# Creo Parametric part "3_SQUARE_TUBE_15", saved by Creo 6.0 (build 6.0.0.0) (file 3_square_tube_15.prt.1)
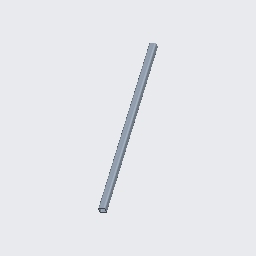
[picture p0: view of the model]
Units: Custom; MM, KILOGRAM, SECS
Materials in the file: STEEL

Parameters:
  BUW_NAME = "SQUARE TUBE"
  BUW_TYPE = "DIN EN 10219"
  BUW_SIZE = "25x25x3.0"
  BUW_LENGTH_STR = "680"
  PTC_MATERIAL_NAME = "STEEL"
  BUW_PROFIL_TYPE = "square_tube"
  BUW_PROFILE_PATH = "parts//profiles/steel_beams_mm/"
  BUW_PROFILE_NAME_LANG = "SQUARE TUBE"
  BUW_TAB_SEL_INFO = "-2 TYPE DIN_EN_10219-1997 SIZE_DINEN_10219 25x25x3.0"
  NAMING = "SQUARE TUBE"
  DESIGNATION = "DIN EN 10219 25x25x3.0 x 680"
  PROFIL_RASTER_POS = "X_0"
  BUW_OBJECT_ROLE = "PROFIL_SYSTEM_BORE_END_POINTS"
  PRO_UNIT_SYS = "Custom"

Other parameters: BUW_LENGTH, LENGTH, BUW_LENGTH_Z_MIN_PARAM, D8, D93, D94, d26, d8, d93, d94, d98, D98, SHEAR_MODULUS, THERM_EXPANSION_REF_TEMPERATURE, STRUCTURAL_DAMPING_COEFFICIENT, STRESS_LIMIT_FOR_TENSION, STRESS_LIMIT_FOR_COMPRESSION, STRESS_LIMIT_FOR_SHEAR, EMISSIVITY

Created from: SQUARE_TUBE.PRT

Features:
  1. datum plane "YZ"
  2. datum plane "XZ"
  3. datum plane "XY"
  4. coordinate system
  5. coordinate system
  6. coordinate system
  7. coordinate system
  8. datum plane "DTM3"
  9. datum plane "DTM4"
  10. datum plane "DTM5"
  11. protrusion
  12. round
  13. round
  14. datum axis
  15. datum point "PNT0"
  16. datum point

Other named items: PROFIL_CUT_QUILT, PROFILE_LENGTH_DIM, CONTACT_SURF_3, CONTACT_SURF_2, CONTACT_SURF_1, CONTACT_SURF_0, E, START_SURFACE, END_SURFACE, SIDE_SURF_3, SIDE_SURF_0, SIDE_SURF_1, SIDE_SURF_2, EDGE_7_S, EDGE_7_E, EDGE_1_S, EDGE_1_E, EDGE_3_S, EDGE_3_E, EDGE_5_S, EDGE_5_E, EDGE_6_S, EDGE_4_S, EDGE_2_S, EDGE_0_S, EDGE_6_E, EDGE_4_E, EDGE_2_E, EDGE_0_E, CS0, CS_S, CS_E, CS3

Named dimensions: X_ROT_S, Y_ROT_S, Z_OFF_S, X_ROT_E, Y_ROT_E, Z_OFF_E, PC_L, BUW_LENGTH_Z_MIN, BUW_LENGTH_DIM

Layers: 00_PROFIL_DATUM, 00_PROFIL_DRW_HIDE, 00_PROFIL_END_CSYS, 00_PROFIL_GEOMETRY, 00_PROFIL_QUILT, 00_PROFIL_SIZE_NOTE

Surfaces: 16 plane, 12 cylinder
